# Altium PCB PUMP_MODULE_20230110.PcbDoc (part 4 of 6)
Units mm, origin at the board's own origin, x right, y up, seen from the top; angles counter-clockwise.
Board outline 260.15 x 142.01 mm, 4 copper layers (Top Layer, Mid-Layer 1, Mid-Layer 2, Bottom Layer); 422 components, 240 nets, 1746 pads, 416 vias.
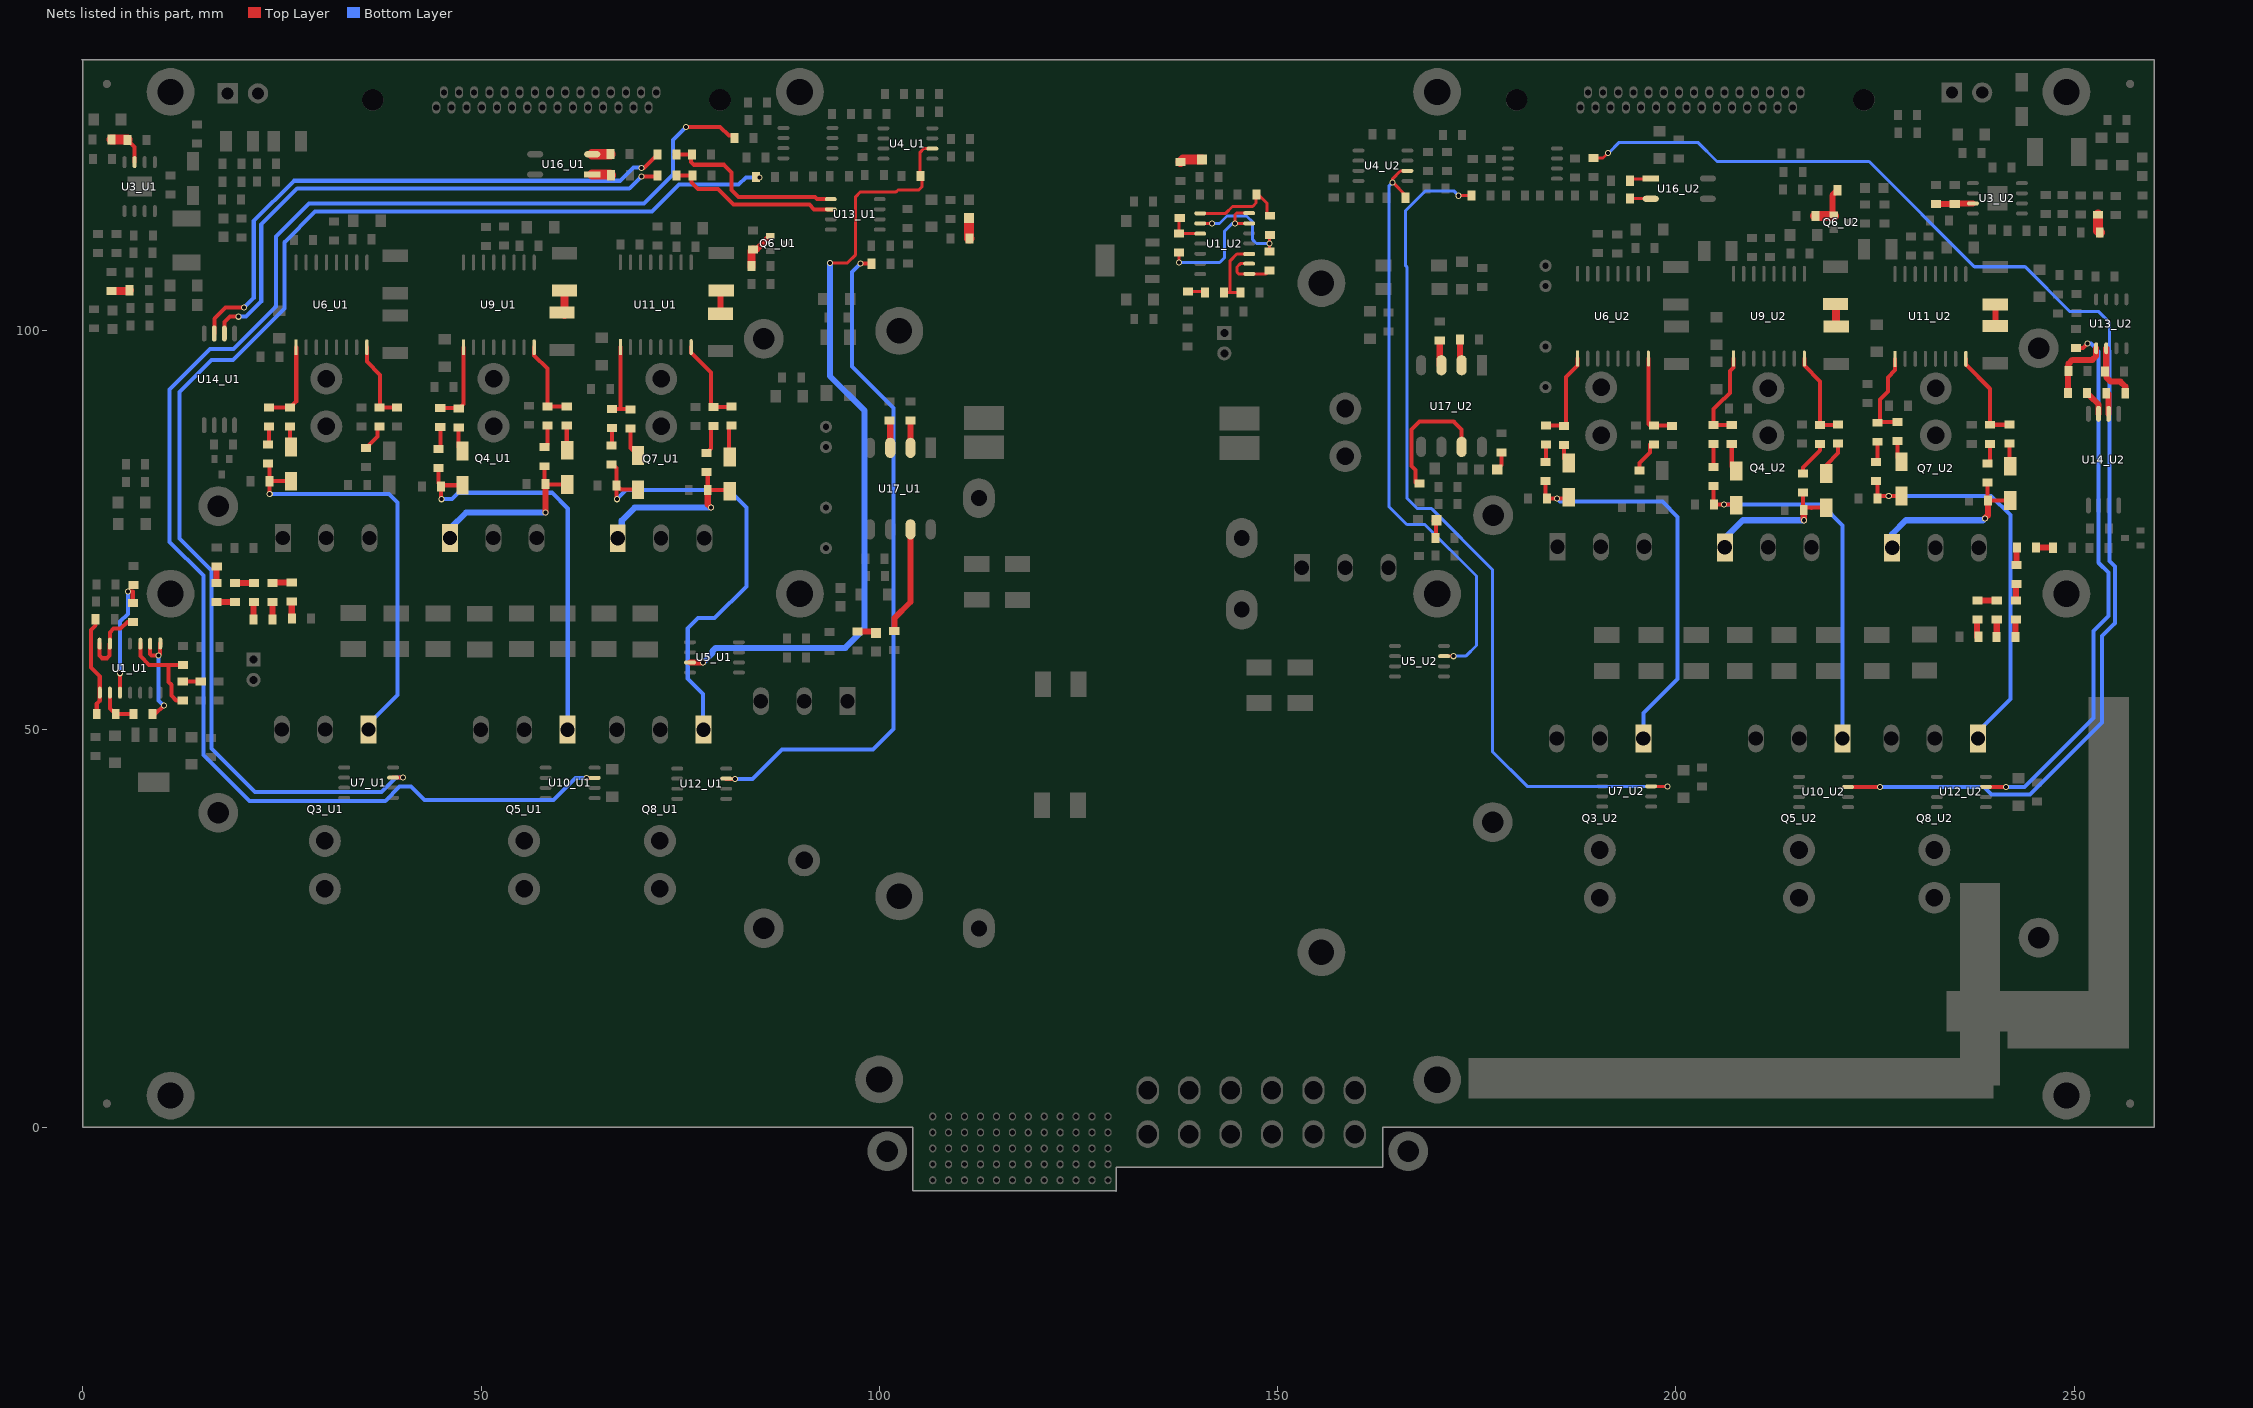
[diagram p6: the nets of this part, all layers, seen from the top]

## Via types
v1: diameter 0.762, hole 0.508, Top Layer to Bottom Layer, 208 vias
v2: diameter 2.032, hole 1.27, Top Layer to Bottom Layer, 78 vias
v3: diameter 1.27, hole 0.762, Top Layer to Bottom Layer, 61 vias
v4: diameter 1.524, hole 1.016, Top Layer to Bottom Layer, 53 vias
v5: diameter 1.27, hole 0.711, Top Layer to Bottom Layer, 16 vias

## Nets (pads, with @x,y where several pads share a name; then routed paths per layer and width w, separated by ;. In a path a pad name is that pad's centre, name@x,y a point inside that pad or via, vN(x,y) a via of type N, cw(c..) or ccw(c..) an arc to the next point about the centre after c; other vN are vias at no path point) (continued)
NetD8_U2_2: D8_U2.2 R34_U2.1 | length 2.4
  Top Layer w0.508: D8_U2.2@177.571,82.601 178.105,83.134 R34_U2.1@178.105,84.76
NetD9_U1_1: D9_U1.1 Q3_U1.1 R36_U1.2 R37_U1.2 | length 53.1
  Top Layer w0.508: R36_U1.2@23.241,83.363 23.444,83.16 R37_U1.2@23.444,81.128 ; v1(23.47,79.502) 23.444,79.527 R37_U1.2@23.444,81.128 ; D9_U1.1@26.137,81.128 R37_U1.2@23.444,81.128
  Bottom Layer w0.508: v1(23.47,79.502) 38.456,79.502 39.497,78.461 39.497,54.28 35.88,50.663 Q3_U1.1@35.88,50
NetD9_U1_2: D9_U1.2 R32_U1.2 | length 2.6
  Top Layer w0.508: R32_U1.2@26.035,87.986 26.035,85.529 D9_U1.2@26.137,85.428
NetD9_U2_1: D9_U2.1 Q3_U2.1 R36_U2.2 R37_U2.2 | length 50.8
  Top Layer w0.508: R36_U2.2@183.617,81.153 183.617,79.121 R37_U2.2@183.794,78.943 v1(185.077,78.943) 186.36,78.943 D9_U2.1@186.538,79.121
  Bottom Layer w0.508: v1(185.077,78.943) 185.458,78.562 198.298,78.562 200.228,76.632 200.228,56.312 195.921,52.005 Q3_U2.1@195.921,48.83
NetD9_U2_2: D9_U2.2 R32_U2.2 | length 2.5
  Top Layer w0.508: R32_U2.2@185.953,85.674 185.953,84.005 D9_U2.2@186.538,83.421
NetD10_U1_1: D10_U1.1 Q4_U1.1 R42_U1.2 R47_U1.2 | length 22.6
  Top Layer w0.508: R42_U1.2@57.963,83.007 57.963,80.899 R47_U1.2@58.064,80.797 58.141,80.721 D10_U1.1@60.833,80.721
  Top Layer w0.762: v1(58.064,77.216) 58.064,78.461 58.09,78.486 58.064,78.511 R47_U1.2@58.064,80.797
  Bottom Layer w0.762: Q4_U1.1@46.12,74 46.12,75.203 48.108,77.191 58.039,77.191 v1(58.064,77.216)
NetD10_U1_2: D10_U1.2 R39_U1.2 | length 3.1
  Top Layer w0.508: R39_U1.2@60.757,88.113 60.757,85.097 D10_U1.2@60.833,85.021
NetD10_U2_1: D10_U2.1 Q4_U2.1 R42_U2.2 R47_U2.2 | length 18.5
  Top Layer w0.508: R42_U2.2@215.951,79.705 215.951,77.622 R47_U2.2@216.052,77.521 216.332,77.8 217.018,77.8 ; 217.041,77.776 217.018,77.8 ; D10_U2.1@218.897,77.8 217.018,77.8
  Top Layer w0.762: R47_U2.2@216.052,77.521 216.052,76.251 v1(216.078,76.225)
  Bottom Layer w0.762: Q4_U2.1@206.146,72.822 206.146,73.965 208.407,76.225 v1(216.078,76.225)
NetD10_U2_2: D10_U2.2 R39_U2.2 | length 4.4
  Top Layer w0.508: D10_U2.2@218.897,82.1 218.897,83.185 220.37,84.658 R39_U2.2@220.37,85.852
NetD11_U1_2: D11_U1.2 D12_U1.1 | length 2.9
  Top Layer w1.016: D12_U1.1@60.477,101.981 D11_U1.2@60.477,104.902
NetD11_U2_2: D11_U2.2 D12_U2.1 | length 2.3
  Top Layer w1.016: D12_U2.1@220.116,100.533 D11_U2.2@220.116,102.819
NetD13_U1_2: D13_U1.2 R46_U1.2 | length 2.4
  Top Layer w0.762: R46_U1.2@97.282,62.255 99.416,62.255 D13_U1.2@99.593,62.078
NetD13_U2_2: D13_U2.2 R46_U2.2 | length 2.4
  Top Layer w0.508: D13_U2.2@169.748,76.124 169.596,76.124 169.875,75.844 R46_U2.2@169.875,73.965
NetD14_U1_1: D14_U1.1 Q5_U1.1 R53_U1.2 R54_U1.2 | length 51.5
  Top Layer w0.508: R53_U1.2@44.679,82.779 44.679,80.874 45.085,80.467 45.237,80.62 D14_U1.1@47.676,80.62 ; R54_U1.2@44.958,80.467 44.958,78.918 v1(45.009,78.867)
  Bottom Layer w0.508: v1(45.009,78.867) 46.33,78.867 47.142,79.68 58.928,79.68 60.884,77.724 60.884,50.004 Q5_U1.1@60.88,50
NetD14_U1_2: D14_U1.2 R49_U1.2 | length 3.1
  Top Layer w0.508: R49_U1.2@47.193,87.859 47.193,85.402 D14_U1.2@47.676,84.92
NetD14_U2_1: D14_U2.1 Q5_U2.1 R53_U2.2 R54_U2.2 | length 47.9
  Top Layer w0.508: R53_U2.2@204.724,80.518 204.724,78.232 R54_U2.2@204.775,78.181 v1(206.045,78.181) 207.493,78.181 D14_U2.1@207.569,78.105
  Bottom Layer w0.508: v1(206.045,78.181) 218.313,78.181 220.921,75.573 Q5_U2.1@220.921,48.83
NetD14_U2_2: D14_U2.2 R49_U2.2 | length 3.6
  Top Layer w0.508: R49_U2.2@207.01,85.801 207.01,82.964 D14_U2.2@207.569,82.405
NetD15_U1_1: D15_U1.1 Q7_U1.1 R61_U1.2 R62_U1.2 | length 21.9
  Top Layer w0.508: R61_U1.2@78.283,82.296 78.461,82.118 R62_U1.2@78.461,80.035 81.026,80.035 D15_U1.1@81.204,79.858
  Top Layer w0.762: R62_U1.2@78.461,80.035 78.461,78.207 78.867,77.8 v1(78.892,77.8)
  Bottom Layer w0.762: Q7_U1.1@67.12,74 67.666,74.546 67.666,76.175 69.291,77.8 v1(78.892,77.8)
NetD15_U1_2: D15_U1.2 R59_U1.2 | length 4
  Top Layer w0.508: R59_U1.2@81.128,88.113 81.128,84.234 D15_U1.2@81.204,84.158
NetD15_U2_1: D15_U2.1 Q7_U2.1 R61_U2.2 R62_U2.2 | length 21.7
  Top Layer w0.508: R61_U2.2@239.116,80.975 239.116,78.689 239.141,78.715 D15_U2.1@241.96,78.715
  Top Layer w0.762: v1(238.785,76.454) 239.166,76.835 R62_U2.2@239.166,78.689
  Bottom Layer w0.762: Q7_U2.1@227.152,72.771 227.152,74.498 228.879,76.225 238.557,76.225 v1(238.785,76.454)
NetD15_U2_2: D15_U2.2 R59_U2.2 | length 2.9
  Top Layer w0.508: R59_U2.2@241.884,85.852 241.884,83.091 D15_U2.2@241.96,83.015
NetD16_U1_2: D16_U1.2 D17_U1.1 | length 2.8
  Top Layer w0.762: D17_U1.1@80.061,102.159 D16_U1.2@80.061,105.004
NetD16_U2_2: D16_U2.2 D17_U2.1 | length 2.7
  Top Layer w0.762: D17_U2.1@240.106,100.635 D16_U2.2@240.106,103.327
NetD18_U1_1: D18_U1.1 Q8_U1.1 R67_U1.2 R68_U1.2 | length 58.1
  Top Layer w0.508: R67_U1.2@66.396,83.236 66.573,83.236 67.031,82.779 R68_U1.2@67.031,80.569 ; v1(67.056,78.867) 67.031,78.892 R68_U1.2@67.031,80.569 ; D18_U1.1@69.698,80.061 67.539,80.061 R68_U1.2@67.031,80.569
  Bottom Layer w0.508: v1(67.056,78.867) 68.199,80.01 81.102,80.01 83.312,77.8 83.312,67.92 79.324,63.932 77.241,63.932 75.946,62.636 75.946,56.363 77.88,54.429 Q8_U1.1@77.88,50
NetD18_U1_2: D18_U1.2 R64_U1.2 | length 3.8
  Top Layer w0.508: R64_U1.2@68.783,87.757 68.783,85.275 D18_U1.2@69.698,84.361
NetD18_U2_1: D18_U2.1 Q8_U2.1 R67_U2.2 R68_U2.2 | length 51.4
  Top Layer w0.508: R67_U2.2@225.12,81.153 225.323,80.95 R68_U2.2@225.323,78.943 225.654,79.273 v1(226.72,79.273) D18_U2.1@228.321,79.273
  Bottom Layer w0.508: v1(226.72,79.273) 239.573,79.273 241.986,76.86 241.986,53.797 237.921,49.733 Q8_U2.1@237.921,48.83
NetD18_U2_2: D18_U2.2 R64_U2.2 | length 2.8
  Top Layer w0.508: R64_U2.2@227.813,86.182 227.813,84.081 D18_U2.2@228.321,83.573
NetD19_U1_2: D19_U1.2 R71_U1.2 | length 2.6
  Top Layer w1.27: D19_U1.2@111.277,114.148 111.277,111.608 R71_U1.2@111.303,111.582
NetD19_U2_2: D19_U2.2 R71_U2.2 | length 2.8
  Top Layer w1.27: R71_U2.2@137.82,121.183 138.151,121.514 D19_U2.2@140.487,121.514
NetQ6_U1_1: Q6_U1.1 R55_U1.1 R58_U1.2 | length 5.1
  Top Layer w0.762: R55_U1.1@84.15,110.236 84.607,110.236 86.081,111.709 Q6_U1.1@86.309,111.709
  Top Layer w1.016: R58_U1.2@83.972,108.001 83.972,110.058 R55_U1.1@84.15,110.236
NetQ6_U2_1: Q6_U2.1 R55_U2.1 R58_U2.2 | length 5.8
  Top Layer w0.762: Q6_U2.1@219.812,114.579 219.634,114.757 219.634,117.018 R55_U2.1@220.269,117.653
  Top Layer w1.27: R58_U2.2@217.449,114.427 R58_U2.2@217.5,114.427 218.948,114.427 Q6_U2.1@219.812,114.427
NetR1_U1_1: R1_U1.1 R5_U1.1 U1_U1.1 | length 12
  Top Layer w0.508: 1.6,63.043 1.016,62.459 1.016,57.734 2.134,56.617 U1_U1.1@2.134,54.585 2.134,53.569 1.753,53.188 R1_U1.1@1.753,51.892
NetR1_U1_2: R1_U1.2 R2_U1.1 U1_U1.2 | length 5.3
  Top Layer w0.508: U1_U1.2@3.404,54.585 3.404,52.578 4.14,51.841 4.191,51.892 R2_U1.1@6.375,51.892
NetR1_U2_1: R1_U2.1 R5_U2.1 U1_U2.1 | length 12.1
  Top Layer w0.381: U1_U2.1@140.284,114.757 143.485,114.757 144.348,115.621 146.863,115.621 147.295,116.053 147.295,117.069 R5_U2.1@147.345,117.119 147.574,117.119 148.641,116.053 148.641,114.859 R1_U2.1@149.047,114.452
NetR1_U2_2: R1_U2.2 R2_U2.1 U1_U2.2 | length 13.9
  Top Layer w0.381: U1_U2.2@140.284,113.487 v1(141.757,113.487) ; R2_U2.1@148.996,109.982 v1(148.996,110.973) 148.996,112.014 R1_U2.2@149.047,112.065
  Bottom Layer w0.381: v1(141.757,113.487) 142.697,113.487 143.637,114.427 146.101,114.427 146.863,113.665 146.863,111.455 147.345,110.973 v1(148.996,110.973)
NetR2_U1_2: R2_U1.2 U1_U1.8 U1_U1.9 | length 12.5
  Top Layer w0.508: U1_U1.9@8.458,60.731 8.458,59.436 8.636,59.258 v1(9.5,59.258) 9.703,59.461 9.703,60.731 U1_U1.8@9.728,60.757 ; R2_U1.2@8.763,51.892 9.093,51.892 v1(10.185,52.984)
  Bottom Layer w0.508: v1(9.5,59.258) 9.5,53.619 v1@10.16,52.959
NetR2_U2_2: R2_U2.2 U1_U2.8 U1_U2.9 | length 6.7
  Top Layer w0.381: U1_U2.9@146.431,108.433 145.313,108.433 144.907,108.026 144.907,107.366 145.161,107.112 146.406,107.112 U1_U2.8@146.456,107.163 148.565,107.163 R2_U2.2@148.996,107.594
NetR3_U1_2: R3_U1.2 R7_U1.1 U1_U1.10 | length 13
  Top Layer w0.508: U1_U1.10@7.239,60.731 7.239,59.157 8.331,58.064 10.77,58.064 ; R7_U1.1@12.548,53.619 11.735,53.619 11.125,54.229 11.125,55.575 10.77,55.931 10.77,58.064 ; R3_U1.2@12.573,58.064 10.77,58.064
NetR3_U2_2: R3_U2.2 R7_U2.1 U1_U2.10 | length 8.8
  Top Layer w0.381: R7_U2.1@143.256,104.8 144.018,104.8 ; R3_U2.2@145.339,104.8 144.018,104.8 ; U1_U2.10@146.431,109.652 144.882,109.652 144.043,108.814 144.043,104.826 144.018,104.8
NetR6_U1_1: R6_U1.1 R12_U1.1 U1_U1.3 | length 15.2
  Top Layer w0.508: U1_U1.3@4.674,54.585 4.674,56.998 v1(4.699,57.023) ; v1(5.664,67.285) 6.274,67.285 6.274,65.913 R6_U1.1@6.325,65.862
  Bottom Layer w0.508: v1(4.699,57.023) 4.699,63.5 5.664,64.465 v1(5.664,67.285)
NetR6_U1_2: R6_U1.2 U1_U1.13 U1_U1.14 | length 9.4
  Top Layer w0.508: U1_U1.14@2.108,60.731 2.108,59.233 2.438,58.903 3.048,58.903 3.378,59.233 3.378,60.706 U1_U1.13@3.404,60.731 3.404,62.154 3.861,62.611 4.75,62.611 5.613,63.475 R6_U1.2@6.325,63.475
NetR6_U2_1: R6_U2.1 R12_U2.1 U1_U2.3 | length 4.7
  Top Layer w0.381: R12_U2.1@137.719,114.173 137.617,114.071 R6_U2.1@137.617,112.217 U1_U2.3@140.284,112.217
NetR6_U2_2: R6_U2.2 U1_U2.13 U1_U2.14 | length 17
  Top Layer w0.381: v1(137.617,108.585) R6_U2.2@137.617,109.83 ; U1_U2.13@146.431,113.487 v1(144.653,113.487) 144.653,114.605 144.831,114.783 U1_U2.14@146.431,114.783
  Bottom Layer w0.381: v1(137.617,108.585) 142.723,108.585 143.358,109.22 143.358,112.547 144.297,113.487 v1(144.653,113.487)
NetR7_U1_2: R7_U1.2 R10_U1.2 | length 2.3
  Top Layer w0.508: R7_U1.2@12.548,56.007 R10_U1.2@14.808,56.007
NetR7_U2_2: R7_U2.2 R10_U2.2 | length 2.2
  Top Layer w0.381: R10_U2.2@138.735,104.927 140.741,104.927 R7_U2.2@140.868,104.8
NetR17_U1_2: R17_U1.2 R24_U1.1 U3_U1.3 | length 5.2
  Top Layer w0.508: R17_U1.2@5.613,123.977 6.502,123.088 U3_U1.3@6.502,121.183
  Top Layer w1.27: R24_U1.1@3.607,124.003 5.588,124.003 R17_U1.2@5.613,123.977
NetR17_U2_2: R17_U2.2 R24_U2.1 U3_U2.3 | length 4.4
  Top Layer w0.762: R24_U2.1@232.664,115.926 234.975,115.926 R17_U2.2@235.001,115.951 ; R17_U2.2@235.255,116.002 U3_U2.3@237.287,116.002
NetR19_U1_2: R19_U1.2 R20_U1.1 | length 2.3
  Top Layer w1.016: R19_U1.2@3.607,105.004 5.791,105.004 R20_U1.1@5.893,105.105
NetR19_U2_2: R19_U2.2 R20_U2.1 | length 2.3
  Top Layer w1.27: R20_U2.1@253.009,114.579 253.009,112.547 R19_U2.2@253.213,112.344
NetR23_U1_1: R23_U1.1 R26_U1.1 U6_U1.8 | length 10
  Top Layer w0.508: U6_U1.8@35.662,97.942 35.662,96.139 37.313,94.488 37.313,90.551 37.465,90.399 R23_U1.1@39.218,90.399
NetR23_U2_1: R23_U2.1 R26_U2.1 U6_U2.8 | length 10.8
  Top Layer w0.508: U6_U2.8@196.545,96.52 196.545,88.29 196.723,88.113 R23_U2.1@199.009,88.113
NetR26_U1_2: R26_U1.2 R27_U1.1 | length 3.3
  Top Layer w0.508: R27_U1.1@35.56,85.293 36.982,86.716 R26_U1.2@36.982,87.986
NetR26_U2_2: R26_U2.2 R27_U2.1 | length 3.8
  Top Layer w0.508: R27_U2.1@195.453,82.474 195.453,83.439 196.723,84.709 R26_U2.2@196.723,85.725
NetR29_U1_2: R29_U1.2 U4_U1.6 U5_U1.7 | length 98
  Top Layer w0.381: v1(93.802,108.534) 95.987,108.534 97.028,109.576 97.028,116.84 97.638,117.45 102.108,117.45 102.337,117.678 ; 102.972,117.678 102.337,117.678 ; R29_U1.2@105.156,119.456 105.131,119.482 105.131,122.428 105.588,122.885 U4_U1.6@106.655,122.885 ; R29_U1.2@105.359,119.507 105.359,118.085 104.953,117.678 102.337,117.678
  Top Layer w0.762: U5_U1.7@76.225,58.369 v1(77.876,58.369)
  Bottom Layer w0.762: v1(77.876,58.369) 79.045,59.538 79.045,59.792 79.451,60.198 95.733,60.198 98.12,62.586 98.12,90.018 93.802,94.336 v1(93.802,108.534)
NetR29_U2_2: R29_U2.2 U4_U2.6 U5_U2.7 | length 74.2
  Top Layer w0.381: R29_U2.2@166.065,116.713 166.141,116.789 166.141,116.942 v1(164.44,118.643) 164.44,119.101 165.43,120.091 U4_U2.6@166.294,120.091 ; U5_U2.7@170.891,59.157 v1(172.06,59.157)
  Bottom Layer w0.381: v1(164.44,118.643) 163.957,118.161 163.957,77.953 166.218,75.692 168.478,75.692 174.955,69.215 174.955,60.503 173.609,59.157 v1(172.06,59.157)
NetR32_U1_1: R32_U1.1 R35_U1.1 U6_U1.1 | length 10.6
  Top Layer w0.508: R35_U1.1@23.368,90.373 R32_U1.1@26.035,90.373 26.797,91.135 26.797,97.917 U6_U1.1@26.772,97.942
NetR32_U2_1: R32_U2.1 R35_U2.1 U6_U2.1 | length 11.3
  Top Layer w0.508: R35_U2.1@183.693,88.138 185.877,88.138 186.207,88.468 186.207,94.209 187.655,95.656 U6_U2.1@187.655,96.52
NetR35_U1_2: R35_U1.2 R36_U1.1 | length 2.3
  Top Layer w0.508: R36_U1.1@23.241,85.75 23.368,85.877 R35_U1.2@23.368,87.986
NetR35_U2_2: R35_U2.2 R36_U2.1 | length 2.2
  Top Layer w0.508: R36_U2.1@183.617,83.541 183.693,83.617 R35_U2.2@183.693,85.75
NetR38_U1_2: R38_U1.2 U17_U1.2 | length 3.4
  Top Layer w0.762: U17_U1.2@103.911,85.319 R38_U1.2@103.911,88.748
NetR38_U2_2: R38_U2.2 U17_U2.2 | length 3.1
  Top Layer w0.762: U17_U2.2@172.898,95.682 172.898,98.755 R38_U2.2@172.923,98.781
NetR39_U1_1: R39_U1.1 R41_U1.1 U9_U1.8 | length 10.5
  Top Layer w0.508: U9_U1.8@56.667,97.942 56.667,96.926 58.318,95.275 R41_U1.1@58.318,90.526 60.731,90.526 R39_U1.1@60.757,90.5
NetR39_U2_1: R39_U2.1 R41_U2.1 U9_U2.8 | length 11.4
  Top Layer w0.508: U9_U2.8@216.129,96.52 216.129,95.631 218.11,93.65 R41_U2.1@218.11,88.189 220.32,88.189 R39_U2.1@220.37,88.24
NetR40_U1_1: R40_U1.1 U17_U1.7 | length 13.6
  Top Layer w0.762: R40_U1.1@101.879,62.332 101.879,63.932 103.911,65.964 U17_U1.7@103.911,75.082
NetR40_U2_1: R40_U2.1 U17_U2.7 | length 16.6
  Top Layer w0.508: R40_U2.1@167.335,80.95 167.335,82.525 166.827,83.033 166.827,87.605 167.818,88.595 172.11,88.595 173.101,87.605 173.101,85.649 172.898,85.446 U17_U2.7@173.177,85.166
NetR41_U1_2: R41_U1.2 R42_U1.1 | length 2.9
  Top Layer w0.508: R42_U1.1@57.963,85.395 58.318,85.75 R41_U1.2@58.318,88.138
NetR41_U2_2: R41_U2.2 R42_U2.1 | length 4.6
  Top Layer w0.508: R42_U2.1@215.951,82.093 215.951,82.855 218.11,85.014 R41_U2.2@218.11,85.801
NetR44_U1_2: R44_U1.2 U7_U1.7 | length 163.6
  Top Layer w0.508: U7_U1.7@38.964,43.917 40.183,43.917 v1(40.208,43.942)
  Bottom Layer w0.508: v1(40.208,43.942) 39.345,43.942 37.49,42.088 21.641,42.088 16.154,47.574 16.154,69.926 12.167,73.914 12.167,92.354 16.18,96.368 18.872,96.368 25.298,102.794 25.298,111.125 29.159,114.986 71.476,114.986 74.854,118.364 82.321,118.364 83.236,119.278 v1(84.963,119.278)
NetR44_U2_2: R44_U2.2 U7_U2.7 | length 108.8
  Top Layer w0.381: v1(172.72,116.967) 172.771,117.018 R44_U2.2@174.32,117.018 ; U7_U2.7@196.901,42.824 v1(198.933,42.824)
  Bottom Layer w0.381: v1(172.72,116.967) 172.11,117.577 168.554,117.577 166.078,115.1 166.078,108.166 166.268,107.975 166.268,78.969 167.564,77.673 169.342,77.673 176.962,70.053 176.962,47.193 181.331,42.824 v1(198.933,42.824)
NetR45_U1_2: R45_U1.2 U17_U1.3 | length 3.5
  Top Layer w0.762: R45_U1.2@101.295,88.773 101.371,88.697 U17_U1.3@101.371,85.319
NetR45_U2_2: R45_U2.2 U17_U2.3 | length 3.1
  Top Layer w0.762: U17_U2.3@170.358,95.682 R45_U2.2@170.358,98.781
NetR49_U1_1: R49_U1.1 R52_U1.1 U9_U1.1 | length 10.3
  Top Layer w0.508: R52_U1.1@44.882,90.297 47.142,90.297 R49_U1.1@47.193,90.246 47.777,90.83 U9_U1.1@47.777,97.942
NetR49_U2_1: R49_U2.1 R52_U2.1 U9_U2.1 | length 12
  Top Layer w0.508: R49_U2.1@207.239,88.417 R49_U2.1@207.01,88.189 R52_U2.1@204.724,88.189 204.724,90.17 206.069,91.515 206.077,91.515 206.781,92.219 206.781,94.971 207.239,95.428 U9_U2.1@207.239,96.52
NetR52_U1_2: R52_U1.2 R53_U1.1 | length 2.8
  Top Layer w0.508: R53_U1.1@44.679,85.166 44.882,85.369 R52_U1.2@44.882,87.909
NetR52_U2_2: R52_U2.2 R53_U2.1 | length 2.9
  Top Layer w0.508: R53_U2.1@204.724,82.906 R52_U2.2@204.724,85.801
NetR57_U1_2: R57_U1.2 U10_U1.7 | length 194.6
  Top Layer w0.508: v1(63.246,43.891) U10_U1.7@64.262,43.891 ; v1(75.717,125.603) 80.01,125.603 81.102,124.511 R57_U1.2@81.915,124.511
  Bottom Layer w0.508: v1(63.246,43.891) 61.874,43.891 59.08,41.097 42.901,41.097 41.224,42.774 39.776,42.774 37.973,40.97 20.904,40.97 15.138,46.736 15.138,69.266 10.897,73.508 10.897,92.659 15.977,97.739 18.923,97.739 24.257,103.073 24.257,111.862 28.372,115.976 70.46,115.976 74.092,119.609 74.092,123.977 v1(75.717,125.603)
NetR57_U2_2: R57_U2.2 U10_U2.7 | length 162.1
  Top Layer w0.381: R57_U2.2@189.636,121.691 190.856,121.691 v1@191.503,122.339
  Top Layer w0.508: U10_U2.7@221.615,42.748 v1(225.628,42.748)
  Bottom Layer w0.381: v1@191.592,122.377 192.888,123.673 202.743,123.673 205.156,121.26 224.257,121.26 237.465,108.052 243.84,108.052 249.479,102.413 253.086,102.413 254.432,101.067 254.432,97.485
  Bottom Layer w0.508: v1(225.628,42.748) 238.658,42.748 239.598,41.808 244.475,41.808 253.517,50.851 253.517,61.697 255.118,63.297 255.118,70.409 254.432,71.095 254.432,97.485
  other v1: 191.465,122.326
NetR59_U1_1: R59_U1.1 R60_U1.1 U11_U1.8 | length 10.8
  Top Layer w0.508: U11_U1.8@76.378,97.968 76.378,97.257 78.842,94.793 78.842,90.449 81.077,90.449 R59_U1.1@81.128,90.5
NetR59_U2_1: R59_U2.1 R60_U2.1 U11_U2.8 | length 12
  Top Layer w0.508: U11_U2.8@236.398,96.495 236.398,95.758 239.42,92.735 R60_U2.1@239.42,88.214 241.859,88.214 R59_U2.1@241.884,88.24
NetR60_U1_2: R60_U1.2 R61_U1.1 | length 3.6
  Top Layer w0.508: R61_U1.1@78.283,84.684 78.842,85.242 R60_U1.2@78.842,88.062
NetR60_U2_2: R60_U2.2 R61_U2.1 | length 2.6
  Top Layer w0.508: R61_U2.1@239.116,83.363 239.42,83.668 R60_U2.2@239.42,85.827
NetR64_U1_1: R64_U1.1 R66_U1.1 U11_U1.1 | length 11.1
  Top Layer w0.508: U11_U1.1@67.488,97.968 67.488,90.297 67.361,90.17 R66_U1.1@66.446,90.17 68.758,90.17 R64_U1.1@68.783,90.145
NetR64_U2_1: R64_U2.1 R66_U2.1 U11_U2.1 | length 11.5
  Top Layer w0.508: U11_U2.1@227.508,96.495 227.508,95.072 226.606,94.17 226.606,92.392 225.603,91.389 225.603,88.773 R66_U2.1@225.298,88.468 225.4,88.57 R64_U2.1@227.813,88.57
NetR66_U1_2: R66_U1.2 R67_U1.1 | length 2.2
  Top Layer w0.508: R67_U1.1@66.396,85.623 66.446,85.674 R66_U1.2@66.446,87.782
NetR66_U2_2: R66_U2.2 R67_U2.1 | length 2.6
  Top Layer w0.508: R67_U2.1@225.12,83.541 225.298,83.718 R66_U2.2@225.298,86.081
NetR70_U1_2: R70_U1.2 U12_U1.7 | length 86
  Top Layer w0.508: U12_U1.7@80.772,43.764 v1(81.89,43.764) v1@81.864,43.79 ; v1@97.612,108.433 R70_U1.2@99.009,108.433
  Bottom Layer w0.508: v1(81.89,43.764) 84.099,43.764 87.782,47.447 99.187,47.447 101.752,50.013 101.752,90.297 96.545,95.504 96.545,107.366 v1@97.612,108.433
  other v1: 97.612,108.458
NetR70_U2_2: R70_U2.2 U12_U2.7 | length 68.1
  Top Layer w0.508: U12_U2.7@238.912,42.748 241.402,42.748 v1(241.427,42.723) ; R70_U2.2@250.241,97.841 251.13,97.841 v1(251.689,98.4) ; R70_U2.2@250.469,97.815 R70_U2.2@250.673,97.815
  Bottom Layer w0.508: v1(241.427,42.723) 243.789,42.723 252.451,51.384 252.451,62.332 254.305,64.186 254.305,69.647 253.06,70.891 253.06,97.434 252.095,98.4 v1(251.689,98.4)
NetR72_U1_1: R72_U1.1 R73_U1.2 U13_U1.5 | length 23.9
  Top Layer w0.508: R73_U1.2@74.295,122.123 76.378,122.123 76.378,121.183 76.708,120.853 80.493,120.853 81.445,119.901 81.445,117.665 82.296,116.815 91.948,116.815 92.202,116.561 U13_U1.5@94.005,116.561
NetR72_U2_1: R72_U2.1 R73_U2.2 U13_U2.5 | length 9.2
  Top Layer w0.762: R73_U2.2@249.225,92.202 249.225,94.513 249.25,94.539 249.25,95.606 ; R72_U2.1@249.301,94.945 249.301,95.885 249.784,96.368 252.273,96.368 252.755,96.85 U13_U2.5@252.755,97.815
NetR73_U1_1: R73_U1.1 U14_U1.7 | length 71.5
  Top Layer w0.508: U14_U1.7@16.51,99.67 16.51,101.524 17.907,102.921 v1(20.244,102.921) ; v1@70.129,120.421 70.46,120.421 R73_U1.1@71.907,121.869
  Bottom Layer w0.508: v1(20.244,102.921) 21.463,104.14 21.463,113.792 26.518,118.847 67.437,118.847 69.113,120.523 v1@70.282,120.523
  other v1: 70.155,120.472
NetR73_U2_1: R73_U2.1 U14_U2.7 | length 3.2
  Top Layer w0.762: R73_U2.1@251.612,92.202 251.993,91.821 253.06,90.754 U14_U2.7@253.06,89.586
NetR74_U1_1: R74_U1.1 R77_U1.2 | length 2.1
  Top Layer w0.762: R74_U1.1@26.238,63.906 R77_U1.2@26.238,66.04
NetR74_U2_1: R74_U2.1 R77_U2.2 | length 2.2
  Top Layer w0.762: R74_U2.1@237.82,61.595 237.82,63.729 R77_U2.2@237.871,63.779
NetR75_U1_1: R75_U1.1 R80_U1.2 | length 2.3
  Top Layer w0.762: R80_U1.2@16.789,65.964 R75_U1.1@19.101,65.964
NetR75_U1_2: R75_U1.2 R76_U1.2 | length 2.4
  Top Layer w0.762: R75_U1.2@19.101,68.351 R76_U1.2@21.488,68.351
NetR75_U2_1: R75_U2.1 R80_U2.2 | length 2.3
  Top Layer w0.762: R75_U2.1@242.773,70.612 242.773,72.669 R80_U2.2@242.951,72.847
NetR75_U2_2: R75_U2.2 R76_U2.2 | length 2.1
  Top Layer w0.762: R76_U2.2@242.697,66.167 242.697,68.148 R75_U2.2@242.773,68.224
NetR76_U1_1: R76_U1.1 R81_U1.2 | length 2.2
  Top Layer w0.762: R81_U1.2@21.412,63.779 21.412,65.888 R76_U1.1@21.488,65.964
NetR76_U2_1: R76_U2.1 R81_U2.2 | length 2.2
  Top Layer w0.762: R81_U2.2@242.646,61.57 242.646,63.729 R76_U2.1@242.697,63.779
NetR77_U1_1: R77_U1.1 R82_U1.2 | length 2.5
  Top Layer w0.762: R82_U1.2@23.8,68.377 23.851,68.428 R77_U1.1@26.238,68.428
NetR77_U2_1: R77_U2.1 R82_U2.2 | length 2.5
  Top Layer w0.762: R77_U2.1@237.871,66.167 R82_U2.2@240.284,66.167 R82_U2.2@240.335,66.116
NetR79_U1_1: R79_U1.1 R80_U1.1 | length 2.1
  Top Layer w0.762: R80_U1.1@16.789,68.351 16.789,70.409 R79_U1.1@16.815,70.434
NetR79_U2_1: R79_U2.1 R80_U2.1 | length 2.2
  Top Layer w0.762: R80_U2.1@245.186,72.796 247.345,72.796 R79_U2.1@247.371,72.771
NetR81_U1_1: R81_U1.1 R82_U1.1 | length 2.2
  Top Layer w0.762: R81_U1.1@23.8,63.779 R82_U1.1@23.8,65.989
NetR81_U2_1: R81_U2.1 R82_U2.1 | length 2.2
  Top Layer w0.762: R81_U2.1@240.259,61.57 240.284,61.595 R82_U2.1@240.284,63.779
NetR83_U1_1: R83_U1.1 R84_U1.2 U13_U1.6 | length 22
  Top Layer w0.508: R84_U1.2@74.32,119.507 76.403,119.507 76.403,118.618 77.216,117.805 79.731,117.805 81.686,115.849 91.237,115.849 91.821,115.265 U13_U1.6@93.904,115.265 U13_U1.6@94.082,115.265
NetR83_U2_1: R83_U2.1 R84_U2.2 U13_U2.6 | length 8.4
  Top Layer w0.762: U13_U2.6@254.025,97.815 254.025,94.615 R83_U2.1@254.063,94.577 ; 254.051,95.656 254.051,94.158 254.584,93.624 255.803,93.624 256.413,93.015 R84_U2.2@256.413,92.177
NetR84_U1_1: R84_U1.1 U14_U1.6 | length 68.9
  Top Layer w0.508: U14_U1.6@17.78,99.67 17.78,101.092 18.466,101.778 v1(19.558,101.778) ; v1(70.129,119.405) 71.831,119.405 R84_U1.1@71.933,119.507
  Bottom Layer w0.508: v1(19.558,101.778) 20.498,101.778 22.403,103.683 22.403,113.36 26.924,117.881 68.605,117.881 v1(70.129,119.405) v1@70.079,119.456
NetR84_U2_1: R84_U2.1 U14_U2.6 | length 2.5
  Top Layer w0.762: U14_U2.6@254.33,89.586 R84_U2.1@254.33,92.1
NetR85_U1_2: R85_U1.2 U16_U1.1 | length 2.4
  Top Layer w1.27: U16_U1.1@63.957,119.634 66.192,119.634 R85_U1.2@66.294,119.532
NetR85_U2_2: R85_U2.2 U16_U2.1 | length 2.3
  Top Layer w0.381: R85_U2.2@194.259,118.415 194.285,118.44 194.285,118.872 194.488,119.075 U16_U2.1@196.012,119.075
NetR86_U1_2: R86_U1.2 U16_U1.3 | length 2.3
  Top Layer w1.27: U16_U1.3@63.957,122.174 66.243,122.174 R86_U1.2@66.269,122.199
NetR86_U2_2: R86_U2.2 U16_U2.3 | length 2.6
  Top Layer w0.381: R86_U2.2@194.259,116.611 196.825,116.611 U16_U2.3@196.85,116.586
